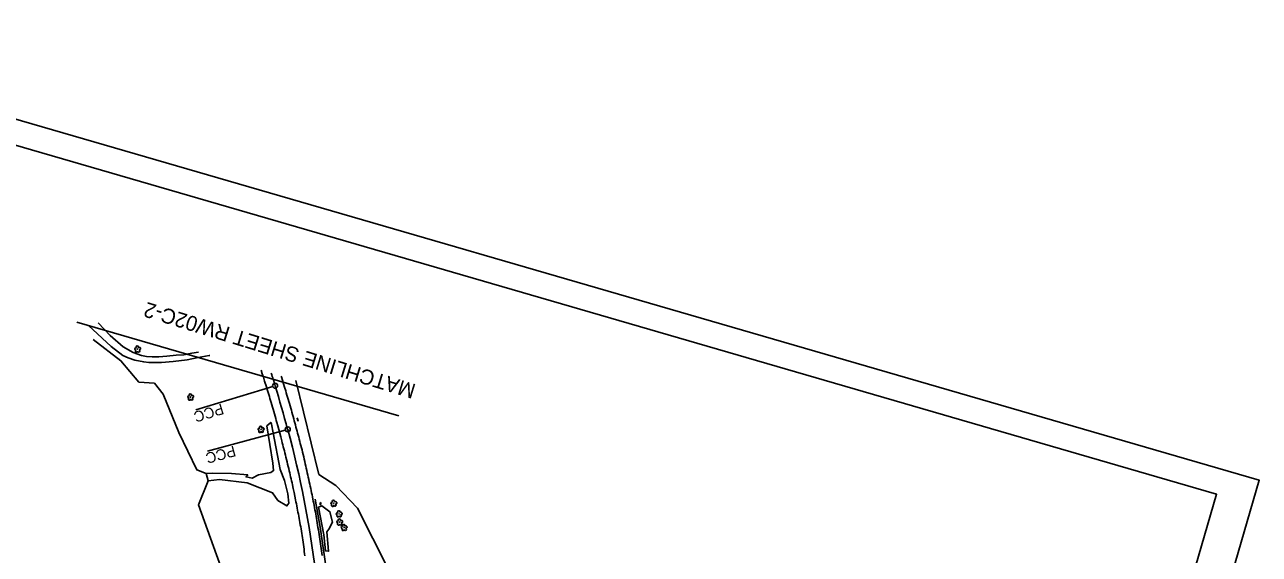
# Model space of a CAD drawing. Extents: x 479429 to 482809, y 488118 to 492379.
# Drawn here: x 480968 to 482809, y 491589 to 492379 of the extents above; entities that cross this region are included whole.
import ezdxf

# ---------------------------------------------------------------- set-up
doc = ezdxf.new("R2010")
doc.units = 0
for name, color, linetype in [('CTL Sheet Border CELL', 7, 'Continuous'), ('Exist Guardrail', 7, 'Continuous'), ('Exist Horizontal Alignment', 7, 'Continuous'), ('Exist Roads EOP', 7, 'Continuous'), ('Exist Roads Soil', 7, 'Continuous'), ('Exist Structure Major Bridge WW', 7, 'Continuous'), ('Exist Structure Minor Head and End Wall', 7, 'Continuous'), ('Exist Vegetation Hedge Row', 7, 'Continuous'), ('Exist Vegetation Tree CELL', 7, 'Continuous'), ('Exist Vegetation Woods Line', 7, 'Continuous'), ('Matchline', 7, 'Continuous'), ('Matchline Text', 7, 'Continuous'), ('Sheet Plot Border Outside CELL', 7, 'Continuous')]:
    doc.layers.add(name, color=color, linetype=linetype)

msp = doc.modelspace()

# ---------------------------------------------------------------- linework, layer by layer
at = {"layer": 'CTL Sheet Border CELL'}
msp.add_lwpolyline([(480512.1, 492327.1), (479585.7, 489136.9), (481818.8, 488488.4), (482745.3, 491678.6)], close=True, dxfattribs=at)
at = {"layer": 'Exist Guardrail'}
msp.add_lwpolyline([(481401.1, 491671), (481408.8, 491626.5), (481417.6, 491564.3), (481423.8, 491502.2), (481426.2, 491466.3), (481427.3, 491437.3), (481427.8, 491395.9), (481427.6, 491358.3), (481426.5, 491320.1)], dxfattribs=at)
at = {"layer": 'Exist Horizontal Alignment'}
for p, q in [((481337.6, 491839.3), (481222.8, 491804.3)), ((481356.4, 491774.3), (481240.6, 491742.8))]:
    msp.add_line(p, q, dxfattribs=at)
for centre in [(481341.2, 491840.4), (481360, 491775.3)]:
    msp.add_circle(centre, 3.75, dxfattribs=at)
for centre, radius, start, end in [((478607.8, 491005.8), 2858, 16.9803, 17.3688), ((479235.2, 491197.3), 2201.9, 15.2158, 16.9803), ((479919.4, 491383.4), 1492.9, 358.5131, 15.2158)]:
    msp.add_arc(centre, radius, start, end, dxfattribs=at)
at = {"layer": 'Exist Roads EOP'}
for points in [[(481385.6, 491586.5), (481385.2, 491589.9), (481384.7, 491593.3), (481384.3, 491596.7), (481383.8, 491600.1), (481383.3, 491603.5), (481382.8, 491607), (481382.3, 491610.3), (481381.8, 491613.7), (481381.3, 491617), (481380.8, 491620.2), (481380.3, 491623.5), (481379.8, 491626.7), (481379.3, 491629.8), (481378.8, 491633), (481378.2, 491636.2), (481377.7, 491639.3), (481377.1, 491642.5), (481376.5, 491645.6), (481375.9, 491648.8), (481375.3, 491651.9), (481374.7, 491654.9), (481374.1, 491658), (481373.5, 491661), (481372.9, 491664), (481372.3, 491667.1), (481371.7, 491670.1), (481370.5, 491675.8), (481369.4, 491681.3), (481368.2, 491686.9), (481367, 491692.6), (481366.4, 491695.6), (481365.7, 491698.5), (481365, 491701.5), (481364.3, 491704.5), (481363.6, 491707.5), (481362.9, 491710.6), (481362.2, 491713.6), (481361.5, 491716.7), (481360.7, 491719.9), (481359.9, 491723.3), (481359.1, 491726.9), (481358.2, 491730.4), (481357.4, 491733.8), (481356.6, 491737), (481355.8, 491740.1), (481355, 491743.2), (481354.2, 491746.2), (481353.4, 491749.2), (481352.7, 491752.2), (481351.9, 491755.2), (481351.2, 491758.1), (481349.7, 491763.9), (481348.2, 491769.5), (481346.8, 491774.9), (481345.3, 491780.3), (481343.8, 491785.7), (481343, 491788.5), (481342.2, 491791.5), (481341.3, 491794.8), (481340.3, 491798.3), (481339.3, 491801.8), (481338.3, 491805.2), (481337.3, 491808.6), (481336.3, 491811.9), (481335.4, 491815.2), (481334.4, 491818.3), (481333.5, 491821.4), (481332.6, 491824.4), (481331.7, 491827.3), (481330, 491833.1), (481328.3, 491838.7), (481327.4, 491841.5), (481326.5, 491844.4), (481325.6, 491847.3), (481323.8, 491853), (481322.1, 491858.3), (481320.5, 491863.3)], [(481350.4, 491854.6), (481350.7, 491853.5), (481352.3, 491848.5), (481353.8, 491843.4), (481355.4, 491838.1), (481357, 491832.5), (481357.9, 491829.6), (481358.8, 491826.5), (481359.8, 491823.3), (481360.7, 491820.1), (481361.6, 491816.9), (481362.6, 491813.6), (481363.5, 491810.3), (481364.5, 491807.1), (481365.4, 491803.9), (481366.3, 491800.7), (481367.1, 491797.5), (481368, 491794.4), (481368.9, 491791.2), (481369.7, 491788.1), (481370.6, 491784.9), (481371.4, 491781.8), (481372.3, 491778.7), (481373.1, 491775.7), (481373.9, 491772.6), (481374.7, 491769.6), (481375.6, 491766.6), (481376.4, 491763.5), (481377.2, 491760.5), (481378, 491757.4), (481378.8, 491754.2), (481379.6, 491751), (481380.5, 491747.8), (481381.3, 491744.5), (481382.1, 491741.1), (481383, 491737.6), (481383.8, 491734.1), (481384.6, 491730.7), (481385.4, 491727.3), (481386.2, 491723.9), (481387, 491720.6), (481387.7, 491717.2), (481388.5, 491713.8), (481389.2, 491710.5), (481390, 491707.2), (481390.7, 491703.8), (481391.5, 491700.4), (481392.2, 491697.1), (481392.9, 491693.7), (481393.6, 491690.4), (481394.3, 491687.2), (481395, 491683.9), (481395.6, 491680.8), (481396.3, 491677.6), (481396.9, 491674.5), (481397.5, 491671.4), (481398.1, 491668.2), (481398.8, 491665.1), (481399.4, 491661.9), (481400, 491658.7), (481400.6, 491655.4), (481401.2, 491652.2), (481401.8, 491649), (481402.3, 491645.7), (481402.9, 491642.5), (481403.5, 491639.2), (481404, 491635.9), (481404.6, 491632.5), (481405.1, 491629.1), (481405.7, 491625.6), (481406.3, 491622.1), (481406.8, 491618.6), (481407.4, 491615.1), (481407.9, 491611.5), (481408.4, 491608), (481409, 491604.4), (481409.5, 491600.9), (481410, 491597.4), (481410.5, 491594), (481411, 491590.6), (481411.4, 491587.2)]]:
    msp.add_lwpolyline(points, dxfattribs=at)
at = {"layer": 'Exist Roads Soil'}
for points in [[(481077.2, 491933.9), (481095.2, 491915), (481114.5, 491898.4)], [(481114, 491885.3), (481096.5, 491898.6), (481063.1, 491930.3)], [(481114.5, 491898.4), (481129.7, 491889.7), (481141.7, 491885.4), (481149.3, 491884.1), (481158, 491883.5), (481167.7, 491883.6), (481179.6, 491884.4), (481193.8, 491885.7), (481205.1, 491886.6), (481217.2, 491888.7), (481227, 491890.4)], [(481243.6, 491885.6), (481242.7, 491885.4), (481226.2, 491882.2), (481210, 491879.1), (481189, 491876.7), (481171.8, 491875.1), (481161.5, 491874.8), (481152.7, 491875.1), (481145.2, 491875.9), (481131.9, 491878.6), (481122.2, 491881.9), (481114, 491885.3)]]:
    msp.add_lwpolyline(points, dxfattribs=at)
at = {"layer": 'Exist Structure Major Bridge WW'}
for p, q in [((481375, 491787.7), (481374, 491791.9)), ((481375.8, 491787.9), (481374.8, 491792.1)), ((481408.2, 491665.8), (481408.6, 491662.9)), ((481409.2, 491666), (481409.6, 491663.1))]:
    msp.add_line(p, q, dxfattribs=at)
at = {"layer": 'Exist Structure Minor Head and End Wall'}
for p, q in [((481374, 491791.9), (481374.8, 491792.1)), ((481375, 491787.7), (481375.8, 491787.9)), ((481408.2, 491665.8), (481409.2, 491666)), ((481408.6, 491662.9), (481409.6, 491663.1))]:
    msp.add_line(p, q, dxfattribs=at)
at = {"layer": 'Exist Vegetation Hedge Row'}
for points in [[(481238.6, 491709.7), (481247.1, 491710.1), (481276, 491709.7), (481300.4, 491707.4), (481298, 491704.4), (481307.2, 491702.6), (481316.3, 491707.4), (481334.9, 491710.7), (481338.8, 491713.7), (481337.7, 491724.8), (481328.8, 491780.3), (481334.6, 491785.7), (481335.6, 491782.8), (481338.2, 491770)], [(481338.2, 491770), (481348.8, 491715.2), (481355.2, 491699), (481360.3, 491679.1), (481361.9, 491665.2), (481358.8, 491661.2), (481345.3, 491669.3), (481337.3, 491680.8), (481299.6, 491695.7), (481258.3, 491700.3), (481241.3, 491698.3)], [(481413.8, 491617.9), (481405.9, 491659.3), (481410.7, 491661.1), (481422.9, 491652.5), (481426.8, 491636.8), (481421.2, 491626.5), (481418.4, 491622.6), (481421, 491593.6), (481416.4, 491593.9), (481413.8, 491617.9)]]:
    msp.add_lwpolyline(points, dxfattribs=at)
at = {"layer": 'Exist Vegetation Tree CELL'}
for p, q in [((481136.2, 491895), (481136.2, 491895)), ((481215.2, 491823.5), (481215.2, 491823.5)), ((481320.2, 491775.3), (481320.2, 491775.3)), ((481428.7, 491665.1), (481428.7, 491665.1)), ((481436.7, 491649.2), (481436.7, 491649.2)), ((481437.6, 491637), (481437.6, 491637)), ((481444.2, 491629), (481444.2, 491629))]:
    msp.add_line(p, q, dxfattribs=at)
for centre in [(481136.2, 491895), (481215.2, 491823.5), (481320.2, 491775.3), (481428.7, 491665.1), (481436.7, 491649.2), (481437.6, 491637), (481444.2, 491629)]:
    msp.add_circle(centre, 0.326, dxfattribs=at)
for centre, radius, start, end in [((481133.5, 491895.2), 1.73, 62.6636, 279.3457), ((481135.8, 491897.9), 1.86, 330.1651, 219.7134), ((481138.7, 491895.6), 1.9, 257.1011, 134.1999), ((481134.4, 491891.9), 1.69, 111.5671, 6.231), ((481137.8, 491892.1), 1.7, 181.2822, 74.56), ((481212.6, 491823.7), 1.73, 62.6636, 279.3457), ((481213.5, 491820.4), 1.69, 111.5671, 6.231), ((481214.8, 491826.4), 1.86, 330.1651, 219.7134), ((481216.9, 491820.6), 1.7, 181.2822, 74.56), ((481217.7, 491824.1), 1.9, 257.1011, 134.1999), ((481317.6, 491775.4), 1.73, 62.6636, 279.3457), ((481318.5, 491772.2), 1.69, 111.5671, 6.231), ((481319.8, 491778.1), 1.86, 330.1651, 219.7134), ((481321.9, 491772.4), 1.7, 181.2822, 74.56), ((481322.8, 491775.9), 1.9, 257.1011, 134.1999), ((481426.1, 491665.2), 1.73, 62.6636, 279.3457), ((481427, 491661.9), 1.69, 111.5671, 6.231), ((481428.3, 491667.9), 1.86, 330.1651, 219.7134), ((481430.4, 491662.2), 1.7, 181.2822, 74.56), ((481431.3, 491665.6), 1.9, 257.1011, 134.1999), ((481434.1, 491649.3), 1.73, 62.6636, 279.3457), ((481435, 491637.2), 1.73, 62.6636, 279.3457), ((481435, 491646.1), 1.69, 111.5671, 6.231), ((481436.3, 491652.1), 1.86, 330.1651, 219.7134), ((481437.2, 491639.9), 1.86, 330.1651, 219.7134), ((481438.4, 491646.3), 1.7, 181.2822, 74.56), ((481439.3, 491649.8), 1.9, 257.1011, 134.1999), ((481440.1, 491637.6), 1.9, 257.1011, 134.1999), ((481435.9, 491633.9), 1.69, 111.5671, 6.231), ((481439.2, 491634.1), 1.7, 181.2822, 74.56), ((481441.6, 491629.1), 1.73, 62.6636, 279.3457), ((481442.5, 491625.9), 1.69, 111.5671, 6.231), ((481443.8, 491631.8), 1.86, 330.1651, 219.7134), ((481445.9, 491626.1), 1.7, 181.2822, 74.56), ((481446.8, 491629.6), 1.9, 257.1011, 134.1999)]:
    msp.add_arc(centre, radius, start, end, dxfattribs=at)
at = {"layer": 'Exist Vegetation Woods Line'}
for points in [[(481070.1, 491909.5), (481111.3, 491877.6), (481138.1, 491845.9), (481161.3, 491844.1), (481174.3, 491827.6)], [(481715.9, 491548), (481655.6, 491556.6), (481653, 491487.6), (481645.4, 491491.1), (481641.1, 491503.1), (481603, 491495.3), (481599.9, 491436.5), (481578.8, 491430.8), (481464.1, 491658), (481431.5, 491691.5), (481406.6, 491708.1), (481372.1, 491848.3)], [(481174.3, 491827.6), (481197.6, 491770.7), (481224.5, 491714.8), (481238.6, 491709.7), (481241.3, 491698.3), (481227, 491662.8), (481282.4, 491508.2), (481313.5, 491469.6), (481314.1, 491441.1), (481314.2, 491405.5), (481345.7, 491317.8)]]:
    msp.add_lwpolyline(points, dxfattribs=at)
at = {"layer": 'Matchline'}
msp.add_line((481045.5, 491934.9), (481525.7, 491795.5), dxfattribs=at)
at = {"layer": 'Sheet Plot Border Outside CELL'}
msp.add_lwpolyline([(481768.9, 488117.8), (482808.9, 491699.3), (480469.5, 492378.7), (479429.4, 488797.2)], close=True, dxfattribs=at)

# ---------------------------------------------------------------- texts
at = {"layer": 'Exist Horizontal Alignment'}
for rotation, p in [(196.9803, (481261.5, 491813.9)), (195.2158, (481279.8, 491751.2))]:
    msp.add_text('PCC', height=16, rotation=rotation, dxfattribs=at).set_placement(p)
at = {"layer": 'Matchline Text'}
msp.add_text('MATCHLINE SHEET RW02C-2', height=22.4, rotation=162.94, dxfattribs=at).set_placement((481552.5, 491842))

doc.saveas('drawing.dxf')
